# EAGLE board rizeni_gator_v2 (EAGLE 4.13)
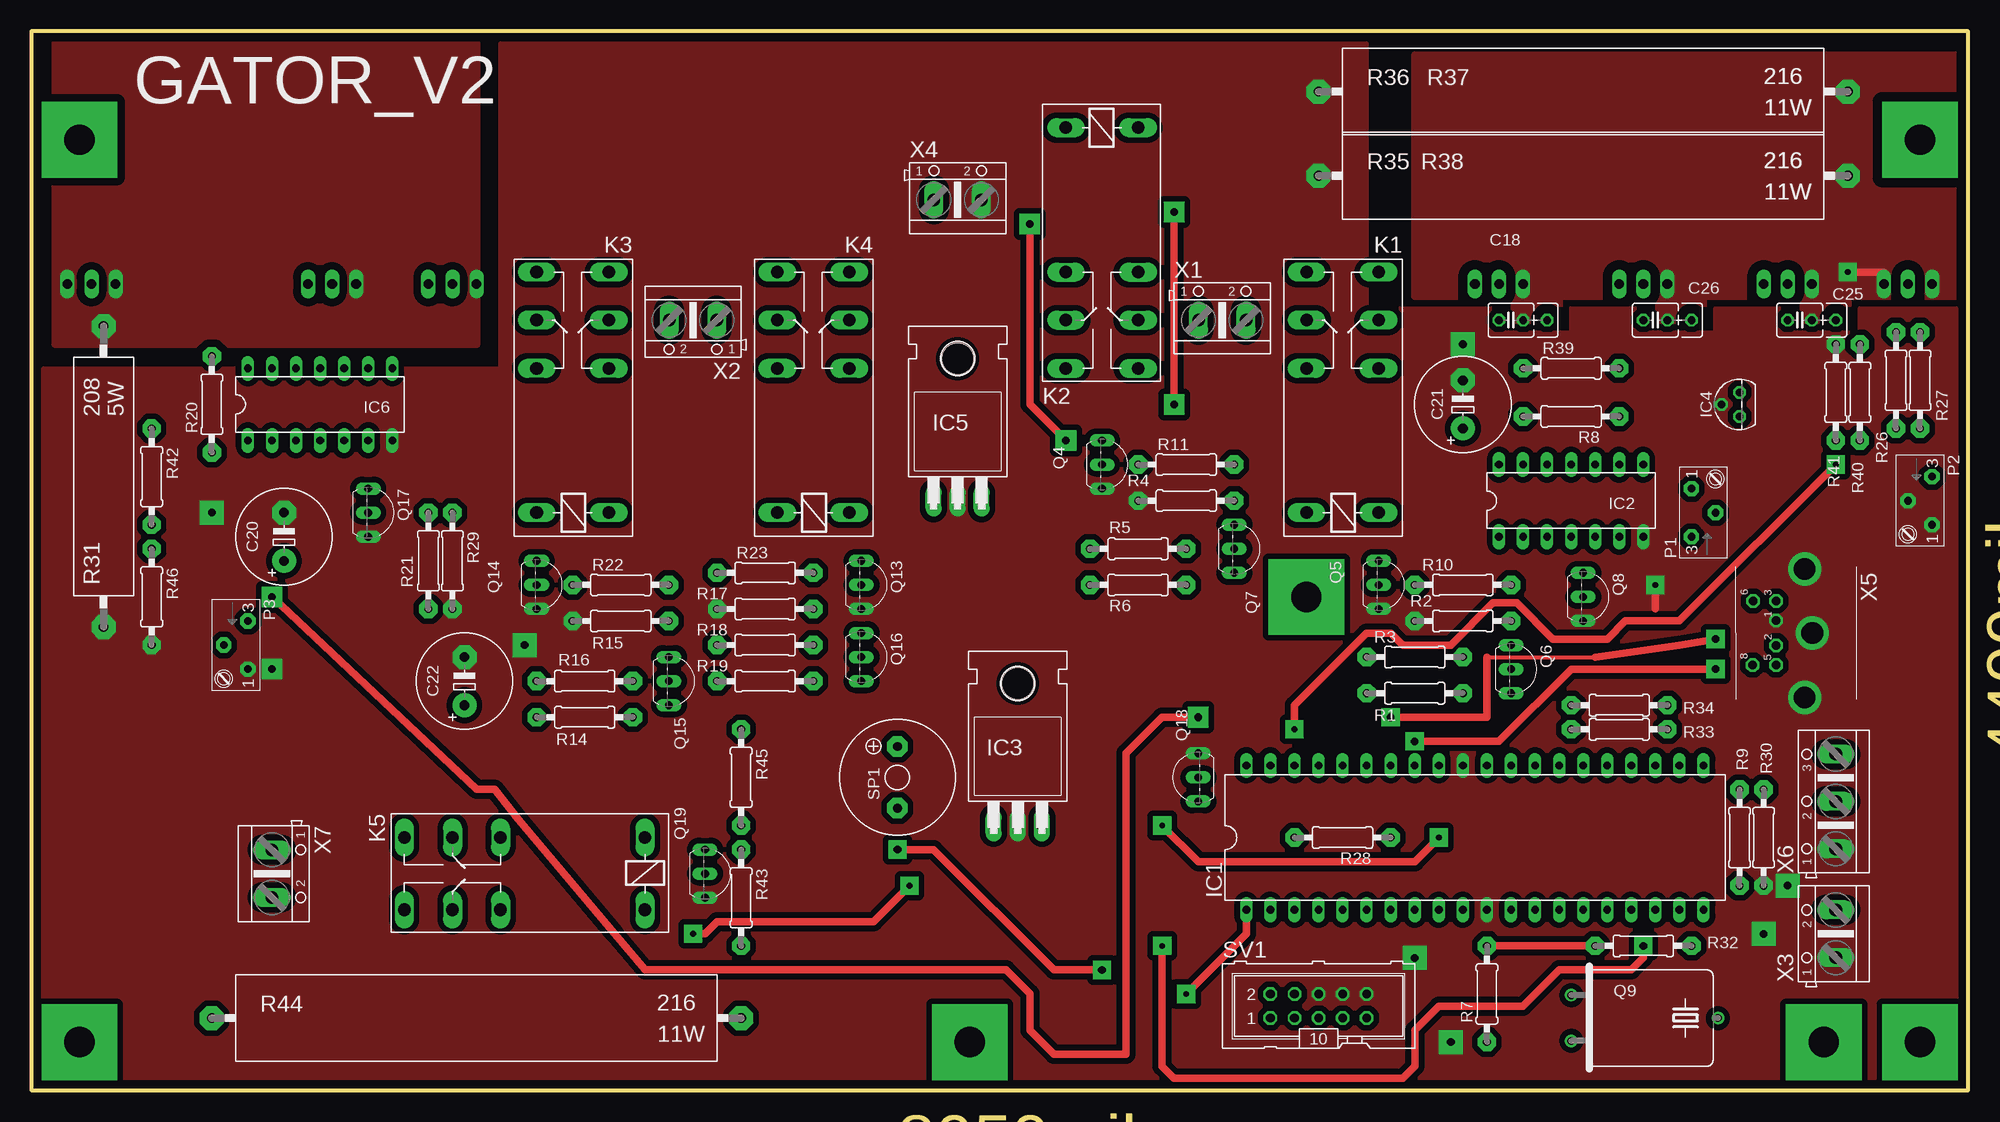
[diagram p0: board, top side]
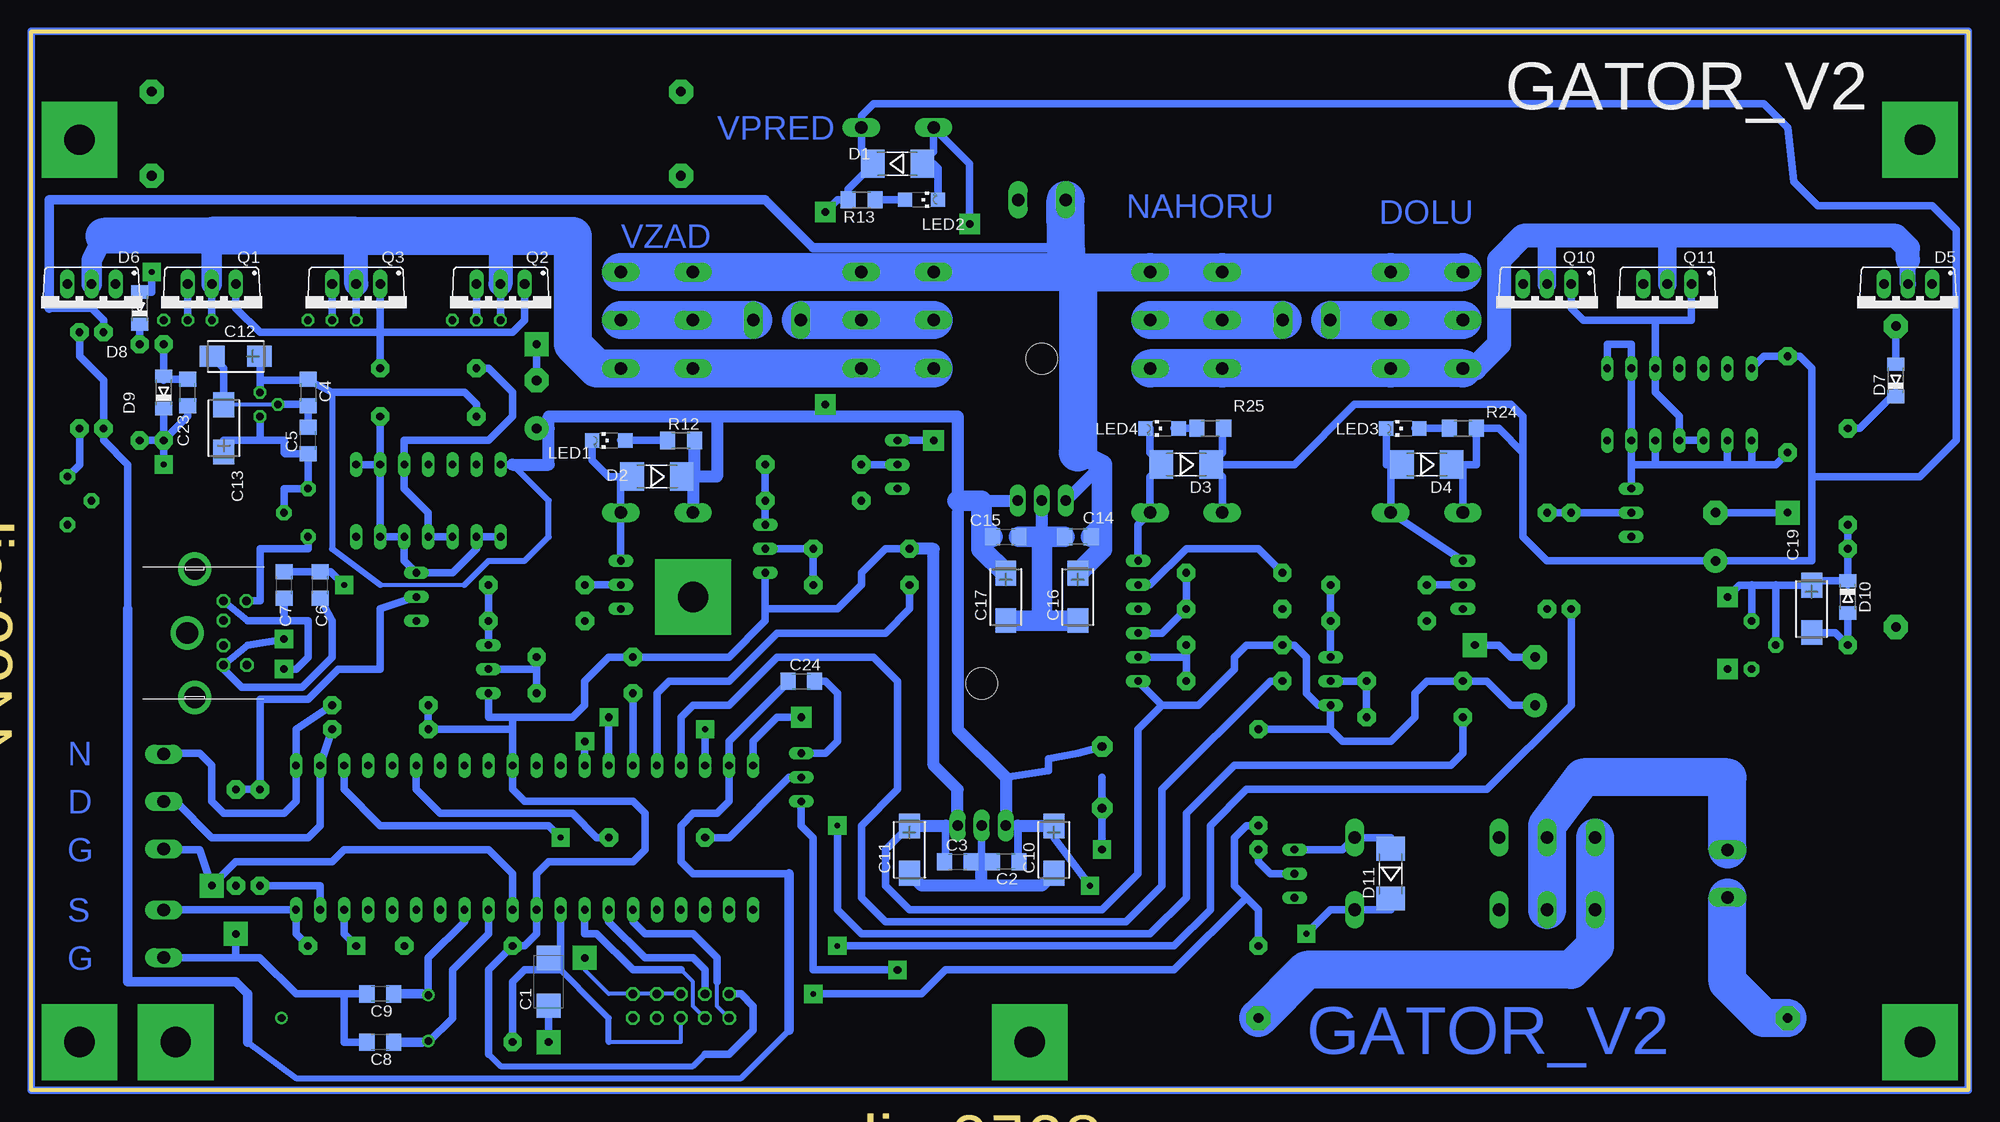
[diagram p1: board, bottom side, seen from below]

Size 204.47 x 111.76 mm. Coordinates in mm from the lower left corner, seen from the top.
Outline: 0,0 204.47,0 204.47,111.76 0,111.76 0,0
Copper layers (1*16): Top 0.035mm / dielectric 1.5mm / Bottom 0.035mm
Design rules "default": minimum track width 0.4mm, minimum drill 0.8mm, track to track 0.4mm, track to pad 0.4mm, pad to pad 0.4mm, via to via 8mil, smd to smd 8mil, copper to edge 0.4mm, drill to drill 0.4mm, minimum pad ring 10mil, minimum via ring 8mil, stop-mask expansion 0mil, vias tented up to drill 0mil, thermal gap 10mil

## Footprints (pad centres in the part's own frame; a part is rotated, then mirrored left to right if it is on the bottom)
C/6032-28R = smd 2.55 x 2.5: + 2.525,0; - -2.525,0
C1206 = smd 1.6 x 1.8: 1 -1.4,0; 2 1.4,0
CT6032 = smd 2.6 x 2.2: + 2.5,0; - -2.5,0
C025_050-035X075 = drill 0.813 octagon: 1 -1.27,0; 2 1.27,0; 3 3.81,0
E5-10,5 = drill 1.016 pad 2.54 round: + -2.54,0 | drill 1.016 pad 2.54 octagon: - 2.54,0
MELF-MLL41 = smd 2.5 x 3: A 2.625,0; C -2.625,0
TO220ABS = drill 1.016 long: A1 -2.54,-2.54; A2 2.54,-2.54; C 0,-2.54
MINIMELF = smd 1.4 x 1.8: A 1.7,0; C -1.7,0
DIL40 = drill 0.813 long: 1 -24.13,-7.62; 2 -21.59,-7.62; 3 -19.05,-7.62; 4 -16.51,-7.62; 5 -13.97,-7.62; 6 -11.43,-7.62; 7 -8.89,-7.62; 8 -6.35,-7.62; 9 -3.81,-7.62; 10 -1.27,-7.62; 11 1.27,-7.62; 12 3.81,-7.62; 13 6.35,-7.62; 14 8.89,-7.62; 15 11.43,-7.62; 16 13.97,-7.62; 17 16.51,-7.62; 18 19.05,-7.62; 19 21.59,-7.62; 20 24.13,-7.62; 21 24.13,7.62; 22 21.59,7.62; 23 19.05,7.62; 24 16.51,7.62; 25 13.97,7.62; 26 11.43,7.62; 27 8.89,7.62; 28 6.35,7.62; 29 3.81,7.62; 30 1.27,7.62; 31 -1.27,7.62; 32 -3.81,7.62; 33 -6.35,7.62; 34 -8.89,7.62; 35 -11.43,7.62; 36 -13.97,7.62; 37 -16.51,7.62; 38 -19.05,7.62; 39 -21.59,7.62; 40 -24.13,7.62
DIL14 = drill 0.813 long: 1 -7.62,-3.81; 2 -5.08,-3.81; 3 -2.54,-3.81; 4 0,-3.81; 5 2.54,-3.81; 6 5.08,-3.81; 7 7.62,-3.81; 8 7.62,3.81; 9 5.08,3.81; 10 2.54,3.81; 11 0,3.81; 12 -2.54,3.81; 13 -5.08,3.81; 14 -7.62,3.81
TO220H = drill 1.118 long: 1 -2.54,-10.16; 2 0,-10.16; 3 2.54,-10.16 | hole 3.302: 0,4.826
TO92 = drill 0.813 octagon: 1 -1.27,0; 2 0,1.905; 3 1.27,0
F4052 = drill 1.321 long: 1 -3.81,3.81; 2 -3.81,-3.81; O1 11.43,-3.81; O2 11.43,3.81; P1 16.51,-3.81; P2 16.51,3.81; S1 21.59,-3.81; S2 21.59,3.81
CHIPLED_1206 = smd 1.5 x 1.5: A 0,-1.75; C 0,1.75
S64Y = drill 0.813 pad 1.6 octagon: 1 2.54,1.27; 2 0,-1.27; 3 -2.54,1.27
TO220BV = drill 1.016 long: D 0,-2.54; G -2.54,-2.54; S 2.54,-2.54
TO92-EBC = drill 0.813 long: B 0,-1.27; C -2.54,-1.27; E 2.54,-1.27
HC49TL-H = drill 0.813 round: 1 -2.413,-7.62; 2 2.413,-7.62; 3 0,7.874
0207/10 = drill 0.813 pad 1.93 octagon: 1 -5.08,0; 2 5.08,0
R1206 = smd 1.6 x 1.803: 1 -1.422,0; 2 1.422,0
KH208-8 = drill 1.016 pad 2.54 octagon: 1 -15.875,0; 2 15.875,0
KH216-8 = drill 1.016 pad 2.54 octagon: 1 -27.94,0; 2 27.94,0
KSS1201 = drill 0.914 pad 2.159 octagon: + 3.251,0; - -3.251,0
ML10 = drill 0.914 octagon: 1 -5.08,-1.27; 2 -5.08,1.27; 3 -2.54,-1.27; 4 -2.54,1.27; 5 0,-1.27; 6 0,1.27; 7 2.54,-1.27; 8 2.54,1.27; 9 5.08,-1.27; 10 5.08,1.27
AK500/2 = drill 1.321 long: 1 -2.515,0; 2 2.515,0
M_DIN6 = drill 0.9 pad 1.422 octagon: 1 -1.3,-3.75; 2 1.3,-3.75; 3 -3.4,-3.75; 5 3.4,-3.75; 6 -3.4,-6.2; 8 3.4,-6.25 | drill 2.3 pad 3.5 round: SH1 6.8,-0.75; SH2 0,0.05; SH3 -6.75,-0.75
AK500/3 = drill 1.321 long: 1 -5.004,0; 2 0,0; 3 5.004,0

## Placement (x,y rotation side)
C1  1M/6V  [C/6032-28R]  149.86,11.43 90 bottom
C2  100NF  [C1206]  101.6,24.13 180 bottom
C3  100NF  [C1206]  106.68,24.13 0 bottom
C4  100NF  [C1206]  175.26,73.66 270 bottom
C5  100NF  [C1206]  175.26,68.58 90 bottom
C6  100NF  [C1206]  173.99,53.34 90 bottom
C7  100NF  [C1206]  177.8,53.34 90 bottom
C8  22P  [C1206]  167.64,5.08 180 bottom
C9  22P  [C1206]  167.64,10.16 180 bottom
C10  10M/16V  [CT6032]  96.52,25.4 90 bottom
C11  10M/6V  [CT6032]  111.76,25.4 90 bottom
C12  10M/16V  [CT6032]  182.88,77.47 0 bottom
C13  10M/6V  [CT6032]  184.15,69.85 270 bottom
C14  100NF  [C1206]  93.98,58.42 180 bottom
C15  100NF  [C1206]  101.6,58.42 0 bottom
C16  10M/35V  [CT6032]  93.98,52.07 90 bottom
C17  10M/16V  [CT6032]  101.6,52.07 90 bottom
C18  10nF/250V  [C025_050-035X075]  156.21,81.28 0 top
C19  2M2/10V  [CT6032]  16.51,50.8 90 bottom
C20  100M/16V  [E5-10,5]  26.67,58.42 90 top
C21  220M/16V  [E5-10,5]  151.13,72.39 90 top
C22  100M  [E5-10,5]  45.72,43.18 90 top
C23  10M/10V  [C1206]  187.96,73.66 90 bottom
C24  10M/10V  [C1206]  123.19,43.18 0 bottom
C25  10nF/250V  [C025_050-035X075]  186.69,81.28 0 top
C26  10nF/250V  [C025_050-035X075]  171.45,81.28 0 top
D1  1N4007  [MELF-MLL41]  113.03,97.79 0 bottom
D2  1N4007  [MELF-MLL41]  138.43,64.77 180 bottom
D3  1N4007  [MELF-MLL41]  82.55,66.04 180 bottom
D4  1N4007  [MELF-MLL41]  57.15,66.04 180 bottom
D5  BYV32  [TO220ABS]  6.35,82.55 180 bottom
D6  BYV32  [TO220ABS]  198.12,82.55 180 bottom
D7  LL101  [MINIMELF]  7.62,74.93 90 bottom
D8  LL101  [MINIMELF]  193.04,82.55 90 bottom
D9  5V1  [MINIMELF]  190.5,73.66 90 bottom
D10  5V1  [MINIMELF]  12.7,52.07 270 bottom
D11  4007  [MELF-MLL41]  60.96,22.86 90 bottom
IC1  ATmega32  [DIL40]  152.4,26.67 0 top
IC2  4001N  [DIL14]  162.56,62.23 0 top
IC3  7805  [TO220H]  104.14,38.1 0 top
IC4  78L05  [TO92]  180.34,72.39 90 top
IC5  7812  [TO220H]  97.79,72.39 0 top
IC6  4001N  [DIL14]  30.48,72.39 0 top
K1  RELEFTR-K1CK012W  [F4052]  138.43,64.77 90 top
K2  RELEFTR-K1CK012W  [F4052]  113.03,97.79 270 top
K3  RELEFTR-K1CK012W  [F4052]  57.15,64.77 90 top
K4  RELEFTR-K1CK012W  [F4052]  82.55,64.77 90 top
K5  RELEFTR-K1CK012W  [F4052]  60.96,22.86 180 top
LED1  RED  [CHIPLED_1206]  143.51,68.58 90 bottom
LED2  RED  [CHIPLED_1206]  110.49,93.98 270 bottom
LED3  RED  [CHIPLED_1206]  59.69,69.85 90 bottom
LED4  RED  [CHIPLED_1206]  85.09,69.85 90 bottom
P1  dle pedalu  [S64Y]  176.53,60.96 90 top
P2  4K7  [S64Y]  199.39,62.23 270 top
P3  100K  [S64Y]  21.59,46.99 270 top
Q1  STP80N1  [TO220BV]  185.42,82.55 180 bottom
Q2  STP80N1  [TO220BV]  154.94,82.55 180 bottom
Q3  STP80N1  [TO220BV]  170.18,82.55 180 bottom
Q4  BC546A  [TO92-EBC]  114.3,66.04 270 top
Q5  BC546A  [TO92-EBC]  143.51,53.34 270 top
Q6  BC556A  [TO92-EBC]  157.48,44.45 270 top
Q7  BC556A  [TO92-EBC]  128.27,57.15 270 top
Q8  BC546A  [TO92-EBC]  165.1,52.07 270 top
Q9  16MHz  [HC49TL-H]  170.18,7.62 270 top
Q10  STP80N1  [TO220BV]  44.45,82.55 180 bottom
Q11  STP80N1  [TO220BV]  31.75,82.55 180 bottom
Q13  BC546A  [TO92-EBC]  88.9,53.34 270 top
Q14  BC546A  [TO92-EBC]  54.61,53.34 270 top
Q15  BC556A  [TO92-EBC]  68.58,43.18 270 top
Q16  BC556A  [TO92-EBC]  88.9,45.72 270 top
Q17  BC546A  [TO92-EBC]  36.83,60.96 270 top
Q18  BC546A  [TO92-EBC]  121.92,33.02 90 top
Q19  BC546A  [TO92-EBC]  72.39,22.86 270 top
R1  1K  [0207/10]  146.05,41.91 0 top
R2  4K7  [0207/10]  151.13,49.53 0 top
R3  10K  [0207/10]  146.05,45.72 180 top
R4  4K7  [0207/10]  121.92,62.23 0 top
R5  10K  [0207/10]  116.84,57.15 180 top
R6  1K  [0207/10]  116.84,53.34 180 top
R7  100K  [0207/10]  153.67,10.16 90 top
R8  10K  [0207/10]  162.56,71.12 180 top
R9  1K  [0207/10]  180.34,26.67 270 top
R10  1K  [0207/10]  151.13,53.34 0 top
R11  1K  [0207/10]  121.92,66.04 0 top
R12  1K  [R1206]  135.89,68.58 0 bottom
R13  1K  [R1206]  116.84,93.98 180 bottom
R14  1K  [0207/10]  58.42,39.37 0 top
R15  4K7  [0207/10]  62.23,49.53 0 top
R16  10K  [0207/10]  58.42,43.18 180 top
R17  4K7  [0207/10]  77.47,50.8 0 top
R18  10K  [0207/10]  77.47,46.99 180 top
R19  1K  [0207/10]  77.47,43.18 180 top
R20  10K  [0207/10]  19.05,72.39 90 top
R21  1K  [0207/10]  41.91,55.88 270 top
R22  1K  [0207/10]  62.23,53.34 0 top
R23  1K  [0207/10]  77.47,54.61 0 top
R24  1K  [R1206]  53.34,69.85 0 bottom
R25  1K  [R1206]  80.01,69.85 0 bottom
R26  82K  [0207/10]  196.85,74.93 90 top
R27  12K  [0207/10]  199.39,74.93 90 top
R28  10K  [0207/10]  138.43,26.67 180 top
R29  100K  [0207/10]  44.45,55.88 270 top
R30  100K  [0207/10]  182.88,26.67 270 top
R31  [KH208-8]  7.62,64.77 90 top
R32  1K  [0207/10]  170.18,15.24 180 top
R33  1K  [0207/10]  167.64,38.1 180 top
R34  1K  [0207/10]  167.64,40.64 180 top
R35  2R2/10W  [KH216-8]  163.83,96.52 0 top
R36  2R2/10W  [KH216-8]  163.83,105.41 0 top
R37  2R2/10W  [KH216-8]  163.83,105.41 0 top
R38  2R2/10W  [KH216-8]  163.83,96.52 0 top
R39  100R  [0207/10]  162.56,76.2 0 top
R40  3K9  [0207/10]  193.04,73.66 90 top
R41  200K  [0207/10]  190.5,73.66 90 top
R42  3K9  [0207/10]  12.7,64.77 270 top
R43  1K  [0207/10]  74.93,20.32 270 top
R44  2R7/10W  [KH216-8]  46.99,7.62 0 top
R45  100K  [0207/10]  74.93,33.02 270 top
R46  200K  [0207/10]  12.7,52.07 270 top
SP1  KSS1201  [KSS1201]  91.44,33.02 90 top
SV1  spicky  [ML10]  135.89,8.89 0 top
X1  ARK500/2  [AK500/2]  125.73,81.28 0 top
X2  ARK500/2  [AK500/2]  69.85,81.28 180 top
X3  ARK500/2  [AK500/2]  190.5,16.51 90 top
X4  ARK500/2  [AK500/2]  97.79,93.98 0 top
X5  MINI-DIN MDD6BB  [M_DIN6]  187.96,48.26 270 top
X6  ARK500/3  [AK500/3]  190.5,30.48 90 top
X7  ARK500/2  [AK500/2]  25.4,22.86 270 top

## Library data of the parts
C1-C26 R1-R30 R32-R34 R39-R43 R45 R46 = rcl
D1-D8 D11 = diode
D9 D10 = diode-1
IC1 = avr-5-4.16
IC2 IC6 = 40xx
IC3-IC5 = linear
K1-K5 = relay
LED1-LED4 = led
P1-P3 = TRIMPOT
Q1-Q3 Q10 Q11 = transistor-power
Q4 Q5 Q8 Q13 Q14 Q17-Q19 = transistor-npn
Q6 Q7 Q15 Q16 = transistor-pnp
Q9 = crystal
R31 R35-R38 R44 = resistor-power
SP1 = buzzer
SV1 = con-harting-ml
X1-X4 X6 X7 = con-ptr500
X5 = mini_din

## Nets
+5V: C3.1 C11.+ C22.+ IC1.10 IC1.30 IC3.3 Q6.E Q7.E Q15.E Q16.E R3.2 R5.2 R7.2 R16.2 R18.2 R32.2 R33.2 R34.2 R45.1 SV1.2
+12V: C2.1 C4.1 C10.+ C12.+ C15.1 C17.+ C20.+ C21.+ D1.C D2.C D3.C D4.C D11.C IC2.14 IC3.1 IC4.3 IC5.3 IC6.14 K1.1 K2.1 K3.1 K4.1 K5.1 R8.2 R12.2 R13.2 R20.2 R24.2 R25.2 SP1.+
+24V: C14.1 C16.+ IC5.1 K1.S1 K1.S2 K2.O1 K2.O2 K3.S1 K3.S2 K4.S1 K4.S2 R26.2 X4.1
AREF: IC1.32
BRZDA: C7.1 IC1.33 X5.3
BRZDA_RELE: IC1.1 R43.2 R45.2
DOLU: IC1.23 R14.1
GND: C1.- C2.2 C3.2 C4.2 C5.2 C6.2 C7.2 C8.2 C9.2 C10.- C11.- C12.- C13.- C14.2 C15.2 C16.- C17.- C19.- C20.- C21.- C22.- C23.2 C24.2 D9.A D10.A IC1.11 IC1.31 IC2.7 IC3.2 IC4.2 IC5.2 IC6.7 P2.1 P2.2 P3.1 Q4.E Q5.E Q8.E Q13.E Q14.E Q17.E Q18.E Q19.E R2.1 R4.1 R15.1 R17.1 R29.2 R30.2 R31.1 R35.1 R36.1 R37.1 R38.1 R41.2 R46.2 SV1.6 SV1.8 SV1.10 X3.1 X4.2 X5.1 X5.SH1 X5.SH2 X5.SH3 X6.1
MISO: IC1.7 SV1.4
MOSI: IC1.6 SV1.1
N$1: D2.A K1.2 LED1.C Q5.C
N$2: C8.1 IC1.12 Q9.2
N$3: K5.P1 K5.P2 X7.1
N$4: R44.1 X7.2
N$5: Q6.B R1.2 R3.1
N$6: Q5.B R10.1
N$7: Q7.B R5.1 R6.1
N$8: C18.1 C25.1 C26.1 D6.C K1.O1 K1.O2 K2.S1 K2.S2 Q1.D Q2.D Q3.D
N$9: D1.A K2.2 LED2.C Q4.C
N$10: Q6.C R2.2 R10.2
N$11: LED1.A R12.1
N$12: Q7.C R4.2 R11.2
N$13: C9.1 IC1.13 Q9.1
N$14: C5.1 C13.+ IC4.1 P1.1 P1.2
N$15: P1.3 X5.6
N$16: Q4.B R11.1
N$17: Q1.G Q2.G Q3.G R39.2
N$18: IC2.1 IC2.2 IC2.5 IC2.6 IC2.8 IC2.9 Q8.C R8.1
N$19: Q8.B R9.1 R30.1
N$20: LED2.A R13.1
N$27: Q18.C SP1.-
N$28: D8.C R40.2
N$29: K3.P1 K3.P2 X2.2
N$30: K4.P1 K4.P2 X2.1
N$31: D4.A K3.2 LED3.C Q14.C
N$32: D3.A K4.2 LED4.C Q13.C
N$33: Q15.C R15.2 R22.2
N$34: Q15.B R14.2 R16.1
N$35: Q16.B R18.1 R19.1
N$36: Q16.C R17.2 R23.2
N$37: D5.C K3.O1 K3.O2 K4.O1 K4.O2 Q10.D Q11.D
N$38: IC6.3 IC6.4 IC6.10 Q10.G Q11.G
N$39: IC6.1 IC6.2 IC6.5 IC6.6 IC6.8 IC6.9 Q17.C R20.1
N$40: Q17.B R21.1 R29.1
N$41: Q14.B R22.1
N$42: Q13.B R23.1
N$43: LED3.A R24.1
N$44: LED4.A R25.1
N$47: Q18.B R28.2
N$48: IC1.26 R28.1
N$49: P2.3 R27.1
N$50: D5.A1 D5.A2 D7.A Q10.S Q11.S R31.2
N$51: K2.P1 K2.P2 X1.1
N$52: C18.2 C25.2 C26.2 D6.A1 D6.A2 D8.A Q1.S Q2.S Q3.S R35.2 R36.2 R37.2 R38.2
N$53: IC2.3 IC2.4 IC2.10 R39.1
N$54: D7.C R42.1
N$55: D11.A K5.2 Q19.C
N$56: Q19.B R43.1
N$57: K1.P1 K1.P2 X1.2
N$58: K5.S1 K5.S2 R44.2
NAHOU: IC1.37 R19.2
NC: SV1.9
PLYN: C6.1 IC1.34 X5.5
PREPINAC_DOLU: IC1.22 R33.1 X6.2
PREPINAC_NAHORU: IC1.21 R34.1 X6.3
PREPINAC_SMER: IC1.20 R32.1 X3.2
PROUD_POHONU: C23.1 D9.C IC1.38 R40.1 R41.1
PROUD_SKL: C19.+ D10.C IC1.40 P3.2 P3.3 R42.2 R46.1
PWM_JIZDY: IC1.19 R9.2
PWM_SKLAPENI: IC1.18 R21.2
RESET: SV1.7
RESET90: C1.+ IC1.9 R7.1 SV1.5
SCK: IC1.8 SV1.3
U_NAP: C24.1 IC1.39 R26.1 R27.2
VPRED: IC1.36 R6.2
VZAD: IC1.35 R1.1

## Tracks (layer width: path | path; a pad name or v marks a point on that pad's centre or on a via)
+5V
  Top 0.813: R7.2 R32.2
  Bottom 0.61: 133.35,3.81 134.62,2.54 154.94,2.54 156.21,3.81
  Bottom 0.813: 127,50.8 127,49.53 130.81,45.72 R3.2 143.51,45.72 146.05,43.18 146.05,40.64 147.32,39.37 153.67,39.37 | 153.67,39.37 156.21,39.37 Q6.E | 153.67,39.37 153.67,38.1 | 153.67,38.1 IC1.30 153.67,31.75 152.4,30.48 140.97,30.48 139.7,29.21 139.7,25.4 140.97,24.13 149.86,24.13 151.13,22.86 IC1.10 151.13,16.51 152.4,15.24 R7.2 156.21,12.7 156.21,3.81 | 127,50.8 Q7.E | 127,50.8 119.38,50.8 116.84,53.34 116.84,54.61 114.3,57.15 R5.2 | C3.1 107.95,24.13 107.95,27.94 IC3.3 | 67.31,38.1 66.04,36.83 60.96,36.83 58.42,39.37 58.42,41.91 57.15,43.18 R16.2 50.8,43.18 48.26,40.64 C22.+ | 67.31,38.1 Q15.E 68.58,40.64 69.85,41.91 69.85,45.72 71.12,46.99 R18.2 76.2,46.99 77.47,45.72 77.47,44.45 81.28,40.64 85.09,40.64 | SV1.2 129.54,10.16 128.27,8.89 128.27,6.35 130.81,3.81 133.35,3.81 | C11.+ 111.76,27.94 114.3,25.4 114.3,21.59 111.76,19.05 91.44,19.05 87.63,22.86 87.63,38.1 85.09,40.64 | R34.2 R33.2 153.67,38.1 | 67.31,38.1 R45.1 | 85.09,40.64 Q16.E
  Bottom 1.27: R5.2 109.22,57.15 109.22,34.29 106.68,31.75 IC3.3 | C11.+ 107.95,27.9 107.95,27.94
+12V  (via drill 0.6 pad 1.93, 0.8 pad 2.18)
  Top 0.813: v120.65,72.39 v120.65,92.71 | v69.85,16.51 71.12,16.51 72.39,17.78 88.9,17.78 v92.71,21.59
  Bottom 0.406: 167.64,53.34 158.75,53.34
  Bottom 0.61: 153.67,66.04 149.86,62.23 149.86,58.42 152.4,55.88 156.21,55.88 158.75,53.34 | 167.64,53.34 172.72,57.15 172.72,73.66
  Bottom 0.813: D2.C 134.62,64.77 134.47,64.92 | 106.68,62.23 106.68,60.96 | 153.67,66.04 IC2.14 | IC4.3 180.34,74.93 | 175.26,74.93 172.72,73.66 158.75,73.66 157.48,72.39 R8.2 | 180.34,74.93 175.26,74.93 | IC3.1 100.33,27.94 100.33,24.13 C2.1 | 175.26,74.93 C4.1 | 54.61,66.04 D4.C 53.34,66.04 | 53.34,66.04 K3.1 | 53.34,66.04 51.92,66.04 R24.2 49.53,69.85 46.99,67.31 | 115.57,97.79 116.84,99.06 K2.1 116.84,102.87 115.57,104.14 21.59,104.14 19.05,101.6 18.41,95.89 15.88,93.34 3.81,93.34 1.27,90.81 1.27,68.58 5.08,64.77 16.51,64.77 | 115.57,97.79 D1.C | 115.57,97.79 118.26,95.1 R13.2 119.38,93.98 v120.65,92.71 | 120.65,71.12 v120.65,72.39 | IC6.14 21.59,77.47 R20.2 17.78,77.47 16.51,76.2 16.51,64.77 | 46.99,67.31 46.99,58.42 44.45,55.88 C20.+ 16.51,55.88 16.51,64.77 | SP1.+ 93.98,35.56 97.08,35 97.08,33.73 101.6,33.02 | 60.96,20.32 D11.C 60.96,19.05 K5.1 67.31,19.05 v69.85,16.51 | v92.71,21.59 96.52,26.67 96.52,27.94 | 80.01,66.04 D3.C 79.92,66.12 78.74,67.31 78.74,69.85 R25.2 | K4.1 78.74,64.77 80.01,66.04 | 80.01,66.04 71.12,66.04 64.77,72.39 48.26,72.39 46.99,71.12 46.99,67.31 | C12.+ 180.34,77.47 180.34,74.93
  Bottom 1.27: K1.1 134.62,64.77 132.08,64.77 132.08,71.12 | 132.08,71.12 120.65,71.12 106.68,71.12 106.68,62.23 | 153.67,66.04 149.86,66.04 149.86,69.85 | 149.86,69.85 149.86,71.12 132.08,71.12 | 106.68,60.96 106.68,38.1 101.6,33.02 IC3.1 | 134.47,64.92 R12.2 | 104.14,62.23 IC5.3 | C10.+ 96.52,27.94 100.33,27.94 | 149.86,69.85 C21.+
  Bottom 2.184: 106.68,62.23 104.14,62.23 104.14,59.69 | C15.1 104.14,59.56 104.14,59.69 | C17.+ 104.14,57.11 104.14,59.69
+24V
  Bottom 0.813: R26.2 196.85,81.28 198.12,82.55 202.56,82.55
  Bottom 1.016: 202.56,82.55 202.56,93.98 127,93.98 121.92,88.9 95.26,88.9 95.25,88.9
  Bottom 1.27: 91.44,66.04 IC5.1
  Bottom 2.184: 93.98,67.31 91.44,66.04 91.44,59.69 | C14.1 91.44,59.56 91.44,59.69 | C16.+ 91.44,57.11 91.44,59.69
  Bottom 4: K1.S1 K1.S2 K2.O2 K2.O1 95.25,86.36 | 95.25,86.36 95.26,88.9 X4.1 | 95.25,86.36 93.98,86.36 | K3.S2 K3.S1 K4.S2 K4.S1 93.98,86.36 | 93.98,86.36 93.98,67.31
BRZDA  (via drill 0.8 pad 1.93)
  Top 0.813: v177.8,44.45 162.56,44.45 154.94,36.83 v146.05,36.83
  Bottom 0.813: X5.3 181.61,49.53 177.8,49.53 | IC1.33 v146.05,36.83 | 177.8,49.53 175.26,49.53 175.26,45.72 176.53,44.45 v177.8,44.45 | 177.8,49.53 C7.1
BRZDA_RELE  (via drill 0.6 pad 1.93)
  Top 0.813: IC1.1 128.27,16.51 v121.92,10.16
  Bottom 0.813: R45.2 76.2,27.94 77.47,26.67 77.47,21.59 76.2,20.32 | 76.2,20.32 74.93,19.05 R43.2 | v121.92,10.16 110.49,10.16 107.95,12.7 83.82,12.7 76.2,20.32
DOLU  (via drill 0.6 pad 1.93)
  Top 0.813: v148.59,26.67 146.05,24.13 123.19,24.13 v119.38,27.94
  Bottom 0.813: R14.1 53.34,35.56 54.61,34.29 77.47,34.29 82.55,29.21 82.55,20.32 86.36,16.51 116.84,16.51 119.38,19.05 v119.38,27.94 | IC1.23 171.45,31.75 167.64,27.94 149.86,27.94 v148.59,26.67
GND  (via drill 0.6 pad 1.93, 0.8 pad 2.18, 0.8 pad 2.54)
  Top 0.813: 171.45,50.8 v171.45,53.34
  Bottom 0.406: v146.05,13.97 146.05,12.7 143.51,10.16 SV1.10 SV1.8 SV1.6 | 184.15,72.39 177.8,72.39
  Bottom 0.813: v149.86,5.08 C1.- | 175.26,72.39 177.8,72.39 IC4.2 | 175.26,72.39 C4.2 | 175.26,72.39 C5.2 | 104.14,24.13 IC3.2 | 102.87,24.13 C2.2 104.14,24.13 | 105.41,24.13 C3.2 104.14,24.13 | IC1.11 153.67,22.86 156.21,25.4 171.45,25.4 172.72,24.13 182.88,24.13 v185.42,21.59 186.69,25.4 190.5,25.4 | 171.45,10.16 176.53,10.16 180.37,13.99 X3.1 | 171.45,10.16 C9.2 | C8.2 171.45,5.08 171.45,10.16 | 182.88,13.97 v182.88,16.51 | v19.05,60.96 C20.- | C21.- v151.13,78.74 | C22.- 48.26,45.72 49.53,46.99 v52.07,46.99 | C13.- 184.15,72.39 184.15,76.2 185.42,77.47 C12.- | R41.2 D9.A 190.5,74.93 190.37,75.06 C23.2 | C7.2 174.12,54.74 173.99,54.61 C6.2 172.85,54.74 v171.45,53.34 | C24.2 120.65,43.18 119.38,41.91 119.38,36.83 120.65,35.56 Q18.E | C19.- 14.01,48.3 R46.2 D10.A
  Bottom 1.27: 97.79,58.42 IC5.2 | C10.- 96.52,22.86 97.79,21.59 104.14,21.59 | C11.- 111.76,22.86 110.49,21.59 104.14,21.59 | 105.41,24.13 104.14,24.13 104.14,21.59
  Bottom 2.184: 97.79,49.53 97.79,58.42 | C16.- 93.98,49.53 97.79,49.53 | C17.- 101.6,49.53 97.79,49.53 | 97.79,58.42 C14.2 | 97.79,58.42 C15.2
  other vias: 25.4,44.45
  pour Top (isolate 0.61, no thermals): 1.27,76.2 49.53,76.2 49.53,110.49 140.97,110.49 140.97,82.55 154.94,82.55 154.94,80.01 162.56,80.01 162.56,82.55 170.18,82.55 170.18,80.01 177.8,80.01 177.8,82.55 185.42,82.55 185.42,80.01 193.04,80.01 193.04,82.55 203.2,82.55 203.2,1.27 1.27,1.27
MISO
  Bottom 0.813: IC1.7 143.51,17.78 139.7,13.97 134.62,13.97 133.35,12.7 SV1.4
MOSI
  Bottom 0.254: 132.08,10.16 132.08,10.79
  Bottom 0.406: 132.08,11.43 132.08,10.16 132.08,8.89 SV1.1
  Bottom 0.813: IC1.6 140.97,17.78 139.7,16.51 134.62,16.51 132.08,13.97 132.08,11.43
N$1
  Bottom 0.813: Q5.C K1.2 142.24,64.77 | 142.24,64.77 D2.A | LED1.C 145.26,66.52 143.51,64.77 142.24,64.77
N$2
  Bottom 0.254: Q9.2 163.19,5.08
  Bottom 0.813: IC1.12 156.21,16.51 160.02,12.7 160.02,7.62 162.56,5.08 Q9.2
  Bottom 1.016: 163.19,5.08 C8.1
N$3
  Bottom 0.813: X7.1 25.4,25.4
  Bottom 4: K5.P2 K5.P1 44.45,27.94 40.64,33.02 25.4,33.02 25.4,25.4
N$4
  Bottom 4: R44.1 21.59,7.62 25.4,11.43 X7.2
N$5
  Bottom 0.813: 151.13,44.45 R3.1 | R1.2 151.13,44.45 | 151.13,44.45 Q6.B
N$6
  Bottom 0.813: Q5.B R10.1
N$7
  Bottom 0.813: Q7.B R5.1 R6.1
N$8
  Bottom 0.813: Q2.D C18.1 | Q3.D C26.1 | Q1.D C25.1
  Bottom 2.184: 185.42,90.17 Q1.D | D6.C 198.12,87.63 196.85,90.17
  Bottom 2.54: 154.94,90.17 Q2.D | Q3.D 170.18,90.17
  Bottom 3.81: 185.42,90.17 196.85,90.17
  Bottom 4: 185.42,90.17 170.18,90.17 154.94,90.17 147.32,90.17 147.32,78.74 144.78,76.2 K1.O1 K1.O2 K2.S2 K2.S1
N$9  (via drill 0.8 pad 2.18)
  Top 0.813: v109.22,68.58 105.41,72.39 v105.41,91.44
  Bottom 0.813: 110.49,97.79 109.22,99.06 K2.2 105.41,97.79 v105.41,91.44 | LED2.C 108.74,97.31 109.22,97.79 110.49,97.79 | 110.49,97.79 D1.A | v109.22,68.58 Q4.C
N$10
  Bottom 0.813: R10.2 R2.2 Q6.C
N$11
  Bottom 0.813: 142.24,68.58 LED1.A R12.1
N$12
  Bottom 0.813: R11.2 R4.2 Q7.C
N$13
  Bottom 0.254: Q9.1 163.19,10.16
  Bottom 0.813: IC1.13 158.75,17.78 162.56,13.97 Q9.1
  Bottom 1.016: 163.19,10.16 C9.1
N$14
  Bottom 0.813: 180.34,68.58 177.8,68.58 177.8,67.31 177.67,67.18 C5.1 | 180.34,68.58 IC4.1 | 184.15,67.31 C13.+ 184.15,68.58 180.34,68.58 | P1.2 177.8,63.5 P1.1 C5.1 | C5.1 175.26,67.31
N$15
  Bottom 0.813: X5.6 180.34,51.66 180.34,57.15 175.26,57.15 P1.3
N$16
  Bottom 0.813: Q4.B R11.1
N$17
  Bottom 0.813: Q2.G 152.4,81.28 153.67,80.01 167.64,80.01 | 167.64,80.01 Q3.G | Q1.G 182.88,82.55 180.34,80.01 167.64,80.01 | 167.64,80.01 R39.2
N$18
  Bottom 0.813: IC2.1 IC2.2 157.48,57.15 160.02,54.61 Q8.C 165.1,55.88 IC2.5 IC2.6 IC2.9 | IC2.9 IC2.8 | IC2.9 R8.1
N$19
  Bottom 0.813: Q8.B 167.64,50.8 167.64,44.45 172.09,44.45 175.26,41.27 180.34,41.27 R9.1 R30.1
N$20
  Bottom 0.813: 115.57,93.98 R13.1 LED2.A
N$21
  Bottom 0.813: 204.47,0 204.47,111.76 0,111.76 0,0 204.47,0
N$22  (via drill 3.2 pad 8)
  other vias: 99.06,5.08
N$23  (via drill 3.2 pad 8)
  other vias: 189.23,5.08
N$24  (via drill 3.2 pad 8)
  other vias: 199.39,5.08
N$25  (via drill 3.2 pad 8)
  other vias: 134.62,52.07
N$26  (via drill 3.2 pad 8)
  other vias: 199.39,100.33
N$27  (via drill 0.8 pad 1.93)
  Top 0.813: v91.44,25.4 95.25,25.4 107.95,12.7 v113.03,12.7
  Bottom 0.813: Q18.C 123.19,27.94 121.92,26.67 121.92,12.7 v113.03,12.7 | v91.44,25.4 SP1.- 91.44,33.02
N$28
  Bottom 0.813: D8.C R40.2
N$29
  Bottom 4: X2.2 K3.P1 K3.P2
N$30
  Bottom 4: K4.P1 K4.P2 X2.1
N$31
  Bottom 0.813: Q14.C K3.2 60.96,66.04 | 59.69,66.04 D4.A 60.96,66.04 | LED3.C 61.44,66.04 60.96,66.04
N$32
  Bottom 0.813: Q13.C 87.63,59.69 K4.2 86.36,64.77 85.09,66.04 D3.A 85.17,66.12 86.36,67.31 86.36,69.85 LED4.C
N$33
  Bottom 0.813: R22.2 R15.2 Q15.C
N$34
  Bottom 0.813: Q15.B R16.1 R14.2
N$35
  Bottom 0.813: R19.1 82.55,45.72 | 82.55,45.72 R18.1 | 82.55,45.72 Q16.B
N$36
  Bottom 0.813: R23.2 R17.2 85.09,48.26 Q16.C
N$37
  Bottom 1.676: D5.C 6.35,87.63
  Bottom 1.93: 31.75,90.17 Q11.D | 44.45,90.17 Q10.D
  Bottom 2.54: K3.O2 52.07,76.2 49.53,78.74 49.53,87.63 46.99,90.17 44.45,90.17 31.75,90.17 7.62,90.17 6.35,88.9 6.35,87.63
  Bottom 4: K3.O2 K3.O1 K4.O2 K4.O1
N$38
  Bottom 0.813: Q10.G 41.91,82.55 40.64,81.28 33.02,81.28 | 33.02,81.28 29.21,81.28 Q11.G | IC6.3 IC6.4 30.48,71.12 33.02,73.66 IC6.10 33.02,81.28
N$39
  Bottom 0.813: 22.86,66.04 IC6.1 | 22.86,66.04 25.4,66.04 | 25.4,66.04 IC6.2 | 33.02,66.04 IC6.5 | 25.4,66.04 33.02,66.04 | 35.56,66.04 IC6.6 IC6.9 35.56,78.74 38.1,78.74 IC6.8 | 33.02,66.04 35.56,66.04 | R20.1 20.32,66.04 22.86,66.04 | 35.56,66.04 Q17.C
N$40
  Bottom 0.813: Q17.B R21.1 R29.1
N$41
  Bottom 0.813: Q14.B R22.1
N$42
  Bottom 0.813: Q13.B 86.36,53.34 82.55,57.15 74.93,57.15 R23.1
N$43
  Bottom 0.813: 58.42,69.85 LED3.A R24.1
N$44
  Bottom 0.813: 81.28,69.85 R25.1 LED4.A 83.82,69.85
N$45  (via drill 3.2 pad 8)
  other vias: 5.08,100.33
N$46  (via drill 3.2 pad 8)
  other vias: 5.08,5.08
N$47
  Bottom 0.813: R28.2 130.81,26.67 124.46,33.02 Q18.B
N$48
  Bottom 0.813: R28.1 144.78,26.67 147.32,29.21 161.29,29.21 163.83,31.75 IC1.26
N$49
  Bottom 0.813: R27.1 199.39,66.04 P2.3
N$50
  Bottom 0.813: D7.A R31.2
  pour Top (isolate 0.813, no thermals): 2.54,110.49 2.54,78.74 46.99,78.74 46.99,110.49
N$51
  Bottom 4: X1.1 K2.P2 K2.P1
N$52  (via drill 0.6 pad 1.93)
  Top 0.813: v191.77,86.36 195.58,86.36 D6.A1
  Bottom 0.813: C18.2 Q2.S | C26.2 Q3.S | C25.2 Q1.S | D8.A 191.77,84.25 v191.77,86.36
  pour Top (isolate 1.016, no thermals): 203.2,83.82 203.2,109.22 146.05,109.22 146.05,83.82 156.21,83.82 156.21,81.28 161.29,81.28 161.29,83.82 171.45,83.82 171.45,81.28 176.53,81.28 176.53,83.82 186.69,83.82 186.69,81.28 191.77,81.28 191.77,83.82
N$53
  Bottom 0.813: IC2.3 IC2.4 162.56,60.96 165.1,63.5 IC2.10 165.1,68.58 156.21,68.58 153.67,71.12 153.67,73.66 156.21,76.2 R39.1
N$54
  Bottom 0.813: D7.C 7.62,73.66 11.43,69.85 R42.1
N$55
  Bottom 0.813: 60.96,25.4 D11.A 60.96,26.67 K5.2 66.04,25.4 Q19.C
N$56
  Bottom 0.813: Q19.B 73.66,22.86 74.93,24.13 R43.1
N$57
  Bottom 4: X1.2 K1.P2 K1.P1
N$58
  Bottom 4: K5.S1 K5.S2 39.37,15.24 41.91,12.7 69.85,12.7 R44.2
NAHOU
  Bottom 0.813: IC1.37 135.89,39.37 134.62,40.64 130.81,40.64 125.73,45.72 115.57,45.72 113.03,43.18 113.03,31.75 116.84,27.94 116.84,20.32 114.3,17.78 88.9,17.78 85.09,21.59 85.09,31.75 73.66,43.18 R19.2
PLYN  (via drill 0.8 pad 1.93)
  Top 0.406: 153.67,45.72 165.1,45.72
  Top 0.813: v177.8,47.62 173.99,46.99 165.1,45.72 | 153.67,45.72 153.67,39.37 v143.51,39.37
  Bottom 0.813: v177.8,47.62 181.61,46.99 X5.5 184.21,44.51 182.25,42.55 175.9,42.55 172.72,45.72 172.72,49.53 C6.1 | IC1.34 v143.51,39.37
PREPINAC_DOLU
  Bottom 0.813: X6.2 189.23,30.48 185.42,26.67 175.26,26.67 173.99,27.94 IC1.22 R33.1
PREPINAC_NAHORU
  Bottom 0.813: X6.3 190.5,35.56 186.69,35.56 185.42,34.29 185.42,30.48 184.15,29.21 177.8,29.21 176.53,30.48 IC1.21 176.53,38.1 R34.1
PREPINAC_SMER
  Bottom 0.813: X3.2 190.5,19.05 IC1.20 176.53,16.51 R32.1
PROUD_POHONU  (via drill 0.6 pad 1.93)
  Top 0.813: v133.35,38.1 133.35,40.64 140.97,48.26 143.51,48.26 144.78,46.99 149.86,46.99 154.31,51.44 156.84,51.44 160.66,47.62 166.37,47.62 168.28,49.53 173.99,49.53 v190.5,66.04
  Bottom 0.813: R41.1 D9.C | R41.1 R40.1 | C23.1 187.96,71.12 R41.1 | v133.35,38.1 IC1.38 | v190.5,66.04 R41.1
PROUD_SKL  (via drill 0.8 pad 2.18)
  Top 0.813: v123.19,39.37 119.38,39.37 115.57,35.56 115.57,3.81 107.95,3.81 105.41,6.35 105.41,10.16 102.87,12.7 64.77,12.7 61.59,16.51 51.44,28.57 48.9,31.75 46.99,31.75 v25.4,52.07
  Bottom 0.813: IC1.40 128.27,36.83 125.73,39.37 v123.19,39.37 | R42.2 R46.1 D10.C | D10.C 12.7,53.34 | D10.C 16.08,53.77 16.51,53.34 C19.+ 20.32,53.3 | 20.32,53.3 22.86,53.3 | 22.86,53.3 24.17,53.3 v25.4,52.07 | 20.32,53.3 20.32,53.34 | P3.2 20.32,53.3 | 22.86,53.3 22.86,53.34 | 22.86,53.3 P3.3
PWM_JIZDY
  Bottom 0.813: R9.2 173.99,21.59 IC1.19
PWM_SKLAPENI  (via drill 0.6 pad 1.93, 0.8 pad 1.93)
  Top 0.813: v170.18,15.24 170.18,13.97 168.91,12.7 161.29,12.7 157.48,8.89 148.59,8.89 146.05,6.35 146.05,2.54 144.78,1.27 120.65,1.27 119.38,2.54 v119.38,15.24
  Bottom 0.813: R21.2 41.91,40.64 50.8,31.75 76.2,31.75 80.01,27.94 80.01,19.05 83.82,15.24 v119.38,15.24 | IC1.18 171.45,16.51 v170.18,15.24
RESET90
  Bottom 0.406: SV1.5 135.89,5.08 143.51,5.08
  Bottom 0.61: 143.51,5.08 143.51,7.62 C1.+
  Bottom 0.813: IC1.9 148.59,12.7 149.86,12.7 | R7.1 153.67,11.43 152.4,12.7 149.86,12.7 | C1.+ 149.86,12.7
SCK
  Bottom 0.406: 135.89,12.7 134.62,11.43 134.62,8.89 SV1.3
  Bottom 0.813: IC1.8 146.05,16.51 144.78,16.51 140.97,12.7 135.89,12.7
U_NAP
  Bottom 0.61: 124.46,6.35 129.54,1.27 176.53,1.27 181.61,5.08
  Bottom 0.813: 124.46,22.86 134.62,22.86 135.89,24.13 135.89,27.94 134.62,29.21 132.08,29.21 130.81,30.48 IC1.39 130.81,36.83 124.46,43.18 C24.1 | R27.2 199.39,77.47 196.85,74.93 R26.1 196.85,68.58 194.31,66.04 194.31,50.8
  Bottom 1.016: 124.46,6.35 124.46,22.86 | 181.61,5.08 181.61,10.16 182.88,11.43 194.31,11.43 194.31,50.8
VPRED
  Bottom 0.813: R6.2 111.76,50.8 114.3,48.26 125.73,48.26 130.81,43.18 137.16,43.18 138.43,41.91 IC1.36
VZAD
  Bottom 0.813: IC1.35 R1.1

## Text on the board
Bottom: VPRED | NAHORU | DOLU | VZAD | N | D | G | S | G | GATOR_V2
Dimension: 4400mil | 8050mil
tPlace: GATOR_V2
bPlace: GATOR_V2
